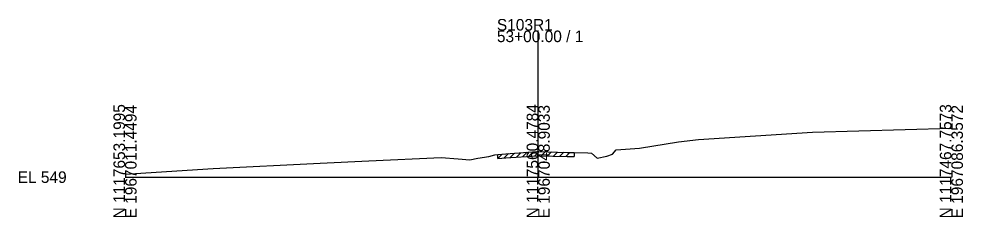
# Model space of a CAD drawing. Extents: x -26 to 203, y -10 to 12018.
# Drawn here: x -25.7 to 202.8, y 990.3 to 1038.4 of the extents above; entities that cross this region are included whole.
import ezdxf

# ---------------------------------------------------------------- set-up
doc = ezdxf.new("R2010")
doc.units = 0
for name, color, linetype in [('Level 60', 7, 'Continuous'), ('Level 61', 7, 'Continuous'), ('Level 63', 7, 'Continuous')]:
    doc.layers.add(name, color=color, linetype=linetype)

msp = doc.modelspace()

# ---------------------------------------------------------------- linework, layer by layer
at = {"layer": 'Level 60'}
for p, q in [((138.76, 1009.14), (166.41, 1010.86)), ((166.41, 1010.86), (200, 1011.84)), ((124.54, 1007.01), (133.98, 1008.53)), ((133.98, 1008.53), (138.76, 1009.14)), ((90.21, 1005.5), (92.18, 1005.66)), ((92.18, 1005.66), (99.7, 1006.2)), ((99.7, 1006.2), (100, 1006.19)), ((100, 1006.19), (106.97, 1006.01)), ((106.97, 1006.01), (108.74, 1005.97)), ((108.74, 1005.97), (112.04, 1005.86)), ((112.04, 1005.86), (112.86, 1005.79)), ((112.86, 1005.79), (114.26, 1004.62)), ((116.57, 1005.06), (117.94, 1005.6)), ((117.94, 1005.6), (118.9, 1006.61)), ((118.9, 1006.61), (124.54, 1007.01)), ((21.35, 1002.12), (47.23, 1003.39)), ((47.23, 1003.39), (58.97, 1003.95)), ((58.97, 1003.95), (76.49, 1004.78)), ((76.49, 1004.78), (80.59, 1004.44)), ((80.59, 1004.44), (83.45, 1004.22)), ((83.45, 1004.22), (85.42, 1004.56)), ((85.42, 1004.56), (88.03, 1005.01)), ((88.03, 1005.01), (89.5, 1005.37)), ((89.5, 1005.37), (90.21, 1005.5)), ((114.26, 1004.62), (116.57, 1005.06)), ((0, 1000.73), (21.35, 1002.12))]:
    msp.add_line(p, q, dxfattribs=at)
at = {"layer": 'Level 61'}
for p, q in [((90.21, 1004.5), (91.3, 1005.59)), ((91.71, 1004.62), (92.79, 1005.7)), ((93.21, 1004.73), (94.29, 1005.81)), ((94.71, 1004.84), (95.79, 1005.92)), ((96.21, 1004.95), (97.29, 1006.03)), ((97.71, 1005.06), (98.79, 1006.14)), ((99.21, 1005.17), (100.23, 1006.19)), ((100.71, 1005.17), (101.69, 1006.15)), ((102.21, 1005.14), (103.19, 1006.11)), ((103.71, 1005.1), (104.69, 1006.07)), ((105.21, 1005.06), (106.19, 1006.03)), ((106.71, 1005.02), (107.69, 1006)), ((108.74, 1005.97), (108.74, 1004.97)), ((90.21, 1004.5), (90.21, 1005.5)), ((90.21, 1004.5), (92.18, 1004.66)), ((92.18, 1004.66), (99.7, 1005.2)), ((99.7, 1005.2), (100, 1005.19)), ((100, 1005.19), (106.97, 1005.01)), ((106.97, 1005.01), (108.74, 1004.97))]:
    msp.add_line(p, q, dxfattribs=at)
at = {"layer": 'Level 63'}
for p, q in [((100, 1000), (100, 1035.52)), ((0, 1000), (100, 1000)), ((100, 1000), (200, 1000))]:
    msp.add_line(p, q, dxfattribs=at)

# ---------------------------------------------------------------- texts
for s, p in [('S103R1', (90, 1035.52)), ('53+00.00 / 1', (90, 1032.72)), ('EL 549', (-26, 998.6))]:
    msp.add_text(s, height=2.8, dxfattribs=at).set_placement(p)
for s, p in [('N 1117653.1995', (0, 990)), ('E 1967011.4494', (2.8, 990)), ('N 1117560.4784', (100, 990)), ('E 1967048.9033', (102.8, 990)), ('N 1117467.7573', (200, 990)), ('E 1967086.3572', (202.8, 990))]:
    msp.add_text(s, height=2.8, rotation=90, dxfattribs=at).set_placement(p)

doc.saveas('drawing.dxf')
